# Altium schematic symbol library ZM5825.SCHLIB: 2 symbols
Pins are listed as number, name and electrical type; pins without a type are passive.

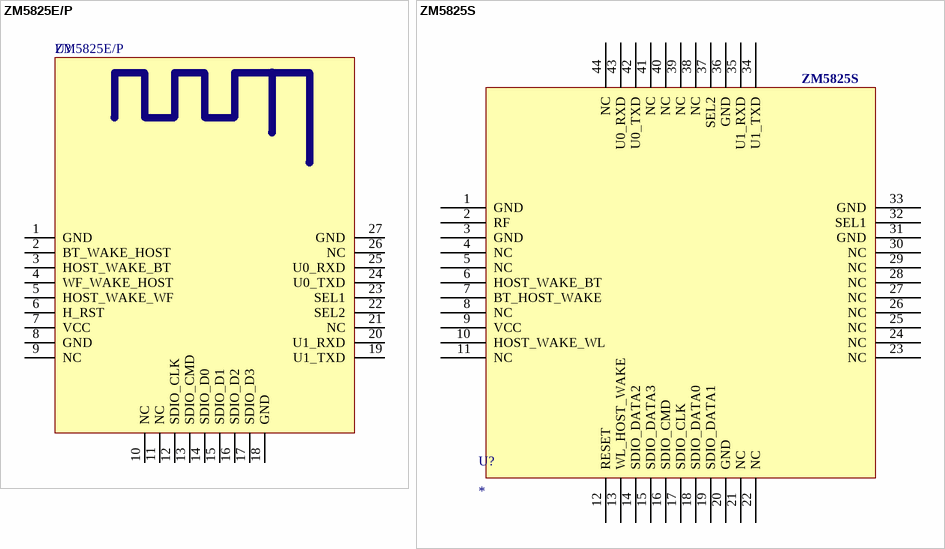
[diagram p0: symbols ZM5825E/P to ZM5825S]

## ZM5825E/P
designator U?
名称: Wi-Fi模块; 厂商: ZHIYUAN; 贴片和直插: SMT; 生产单位: PCS
pins: 1 GND, 2 BT_WAKE_HOST, 3 HOST_WAKE_BT, 4 WF_WAKE_HOST, 5 HOST_WAKE_WF, 6 H_RST, 7 VCC, 8 GND, 9 NC, 10 NC, 11 NC, 12 SDIO_CLK, 13 SDIO_CMD, 14 SDIO_D0, 15 SDIO_D1, 16 SDIO_D2, 17 SDIO_D3, 18 GND, 19 U1_TXD, 20 U1_RXD, 21 NC, 22 SEL2, 23 SEL1, 24 U0_TXD, 25 U0_RXD, 26 NC, 27 GND

## ZM5825S
designator U?
ZM5825S
pins: 1 GND (power), 2 RF, 3 GND (power), 4 NC, 5 NC, 6 HOST_WAKE_BT, 7 BT_HOST_WAKE, 8 NC, 9 VCC (power), 10 HOST_WAKE_WL, 11 NC, 12 RESET, 13 WL_HOST_WAKE, 14 SDIO_DATA2, 15 SDIO_DATA3, 16 SDIO_CMD, 17 SDIO_CLK, 18 SDIO_DATA0, 19 SDIO_DATA1, 20 GND (power), 21 NC (power), 22 NC (power), 23 NC (power), 24 NC, 25 NC, 26 NC, 27 NC, 28 NC, 29 NC, 30 NC, 31 GND (power), 32 SEL1, 33 GND (power), 34 U1_TXD, 35 U1_RXD, 36 GND (power), 37 SEL2, 38 NC, 39 NC, 40 NC, 41 NC, 42 U0_TXD, 43 U0_RXD, 44 NC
